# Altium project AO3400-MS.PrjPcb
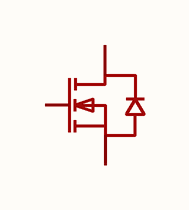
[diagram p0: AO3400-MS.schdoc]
1 sheet, 1 parts. Net scope: global (net labels, ports and power ports of the same name join across sheets).

## Sheet AO3400-MS.schdoc
size 127 x 101 mm

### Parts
U?  ao3400-ms  [SOT-23-3_L2.9-W1.6-P1.90-LS2.8-BR]  (value not drawn)

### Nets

Not connected (* = marked no-connect by the designer): U? 1(G) 2(S) 3(D)

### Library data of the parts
U? = ao3400-ms: 数量:1个N沟道;漏源电压(Vdss):30V;连续漏极电流(Id):5.8A;导通电阻(RDS(on)):30mΩ@10V;耗散功率(Pd):1.56W;阈值电压(Vgs(th)):1.2V;; Manufacturer: MSKSEMI(美森科); AddInBom: yes; ModelId: 89cb27a44ab2466697082bb9fd73a7d0; ModelName: SOT-23-3L_L2.9-W1.6-H1.1-LS2.8-P0.95; ModelTransform: 114.173,110.236,0,90,0,0,0,0,0; Number: 1个N沟道; Drain to Source Voltage: 30V; Current - Continuous Drain(Id): 5.8A; Pd - Power Dissipation: 1.56W; Gate Threshold Voltage (Vgs(th)): 1.2V; Gate Charge(Qg): 4.1nC@4.5V; Input Capacitance(Ciss): 345pF; Reverse Transfer Capacitance (Crss@Vds): 32pF; Output Capacitance(Coss): 55pF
